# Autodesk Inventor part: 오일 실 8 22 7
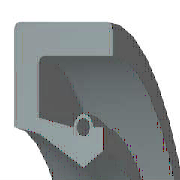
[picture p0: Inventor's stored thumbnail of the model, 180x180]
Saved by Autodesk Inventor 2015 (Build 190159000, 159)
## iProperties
IsCustomPart: 1
Created: 2012-02
Part Number: 오일 실 8 22 7
Material: 고무
Description: 오일-실
Document SubType Name: Modeling
Standard: KS B 2804
Designer: test
Standards Organization: KS
Language: ko-KR
Size Designation: S - 8 22 7
Categories: <MemberInstance><Categories><Category DisplayName="샤프트 부품" InternalName="7f7aeb1f-a693-4053-b835-cee3144e0d98" Mnemonic="SHFT"><Category DisplayName="실링" Intern
Density: 0.93 g/cm^3
Appearance: 고무 - 검은색 - 버전 1.1
Mass: 1.07912 g
Surface Area: 17.6852 cm^2
Volume: 1.16034 cm^3
Author: test
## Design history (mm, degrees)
revolve "본체" stored, may be unused: angle "d17" = 90 deg
revolve "스프링1" stored, may be unused: angle "d18" = 90 deg
body "Solid1"
sketch "스케치1"
  geometry: L1 (0, 11)-(7, 11); L2 (7, 11)-(7, 9.75); L3 (7, 9.75)-(1.75, 9.75); L4 (0, 11)-(0, 6.1); L5 (0, 6.1)-(1.75, 5.75); L6 (1.75, 5.75)-(4.9, 4); L7 (4.9, 4)-(0, 4); L8 (6.3, 4.875)-(6.3, 6.1); L9 (0, 0)-(9.586, 0) reference; L10 (4.9, 4)-(6.3, 4.875); L11 (0, 18)-(0, -3) reference; L12 (-1.917, 0)-(11.503, 0) reference; L13 (4.2, 6.1)-(1.75, 6.59); L14 (1.75, 6.59)-(1.75, 9.75); L15 (6.3, 6.1)-(5.6, 6.1); C1 r 0.455 at (4.9, 6.1); A1 r 0.7 centre (4.9, 6.1) between (5.6, 6.1) and (4.2, 6.1)
  constraints: 26 end point, 5 horizontal alignment, 4 perpendicular, 2 centre point, 2 collinear, 2 horizontal, 2 parallel, 2 point on circle, 2 point on line, 2 vertical alignment, 1 coincident
  dimensions: "d0" = 22 diameter of L1 L9 (= SD2); "d1" = 9.75 diameter of L8.start L9 (= ABDM); "d2" = 1.25 distance of L1.end L2.end (computed from SD); "d3" = 0.91 diameter of C1 (= SPDI); "d4" = 1.4 diameter of A1 (= SPDA); "d5" = 8 diameter of L6.end L9 (= NND); "d6" = 11.5 diameter of L5.end L9 (= TKDM); "d7" = 12.2 diameter of L4.end L9 (= HLDM); "d8" = 4.9 distance from line of C1.centre L4 (= SPDST); "d9" = 6.3 distance between parallel lines of L8 L4 (= SDI); "d10" = 7 distance between parallel lines of L2 L4 (= SWDT); "d12" = 1.75 distance between parallel lines of L14 L4 (= SD)
fillet "모깎기1" dims "d11" = 0.3 (= RR)
other parameters: "SD2" = 22 [user parameter; used in 1 equation term], "SWDT" = 7 [user parameter; used in 1 equation term], "RR" = 0.3 [user parameter; used in 1 equation term], "SD" = 1.75 [user parameter; used in 2 equation terms], "NND" = 8 [user parameter; used in 1 equation term], "SPDA" = 1.4 [user parameter; used in 1 equation term], "SPDI" = 0.91 [user parameter; used in 1 equation term], "TKDM" = 11.5 [user parameter; used in 1 equation term], "HLDM" = 12.2 [user parameter; used in 1 equation term], "ABDM" = 9.75 [user parameter; used in 1 equation term], "SDI" = 6.3 [user parameter; used in 1 equation term], "SPDST" = 4.9 [user parameter; used in 1 equation term], "d13" = 0, "d14" = 0, "d15" = 0, "LAB" = 0.35 [user parameter]
